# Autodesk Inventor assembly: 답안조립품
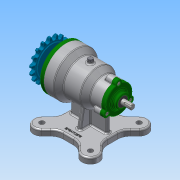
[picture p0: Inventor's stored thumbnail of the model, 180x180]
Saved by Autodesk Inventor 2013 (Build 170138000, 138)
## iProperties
Created: 2017-03
Part Number: 답안조립품
Document SubType Name: Assembly
Designer: Administrator
Author: Administrator
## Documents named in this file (14)
- C:\Users\Administrator\Desktop\470308V1004\470308V1004\답안조립품.iam
- C:\Users\Administrator\Desktop\470308V1004\470308V1004\본체.ipt
- C:\Users\Administrator\Desktop\470308V1004\470308V1004\뒤커버.ipt
- C:\Users\Administrator\Desktop\470308V1004\470308V1004\베어링-6200.ipt
- C:\Users\Administrator\Desktop\470308V1004\470308V1004\베어링-6203.ipt
- C:\Users\Administrator\Desktop\470308V1004\470308V1004\볼트 M4 x 12.ipt
- C:\Users\Administrator\Desktop\470308V1004\470308V1004\볼트 M5 x 10.ipt
- 볼트 M5 x 10.ipt
- C:\Users\Administrator\Desktop\470308V1004\470308V1004\스프로킷.ipt
- C:\Users\Administrator\Desktop\470308V1004\470308V1004\앞커버.ipt
- C:\Users\Administrator\Desktop\470308V1004\470308V1004\오일 실 10 20 7.ipt
- C:\Users\Administrator\Desktop\470308V1004\470308V1004\오일 실 17 30 8.ipt
- C:\Users\Administrator\Desktop\470308V1004\470308V1004\축.ipt
- C:\Users\Administrator\Desktop\470308V1004\470308V1004\키5x5.ipt
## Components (9 placed, 1 different names)
1. ISO 4762 M4 x 12:1
2. ISO 4762 M4 x 12:2
3. ISO 4762 M4 x 12:3
4. ISO 4762 M4 x 12:4
5. ISO 4762 M4 x 12:5
6. ISO 4762 M4 x 12:6
7. ISO 4762 M4 x 12:7
8. ISO 4762 M4 x 12:8
9. ISO 4762 M4 x 12:9
